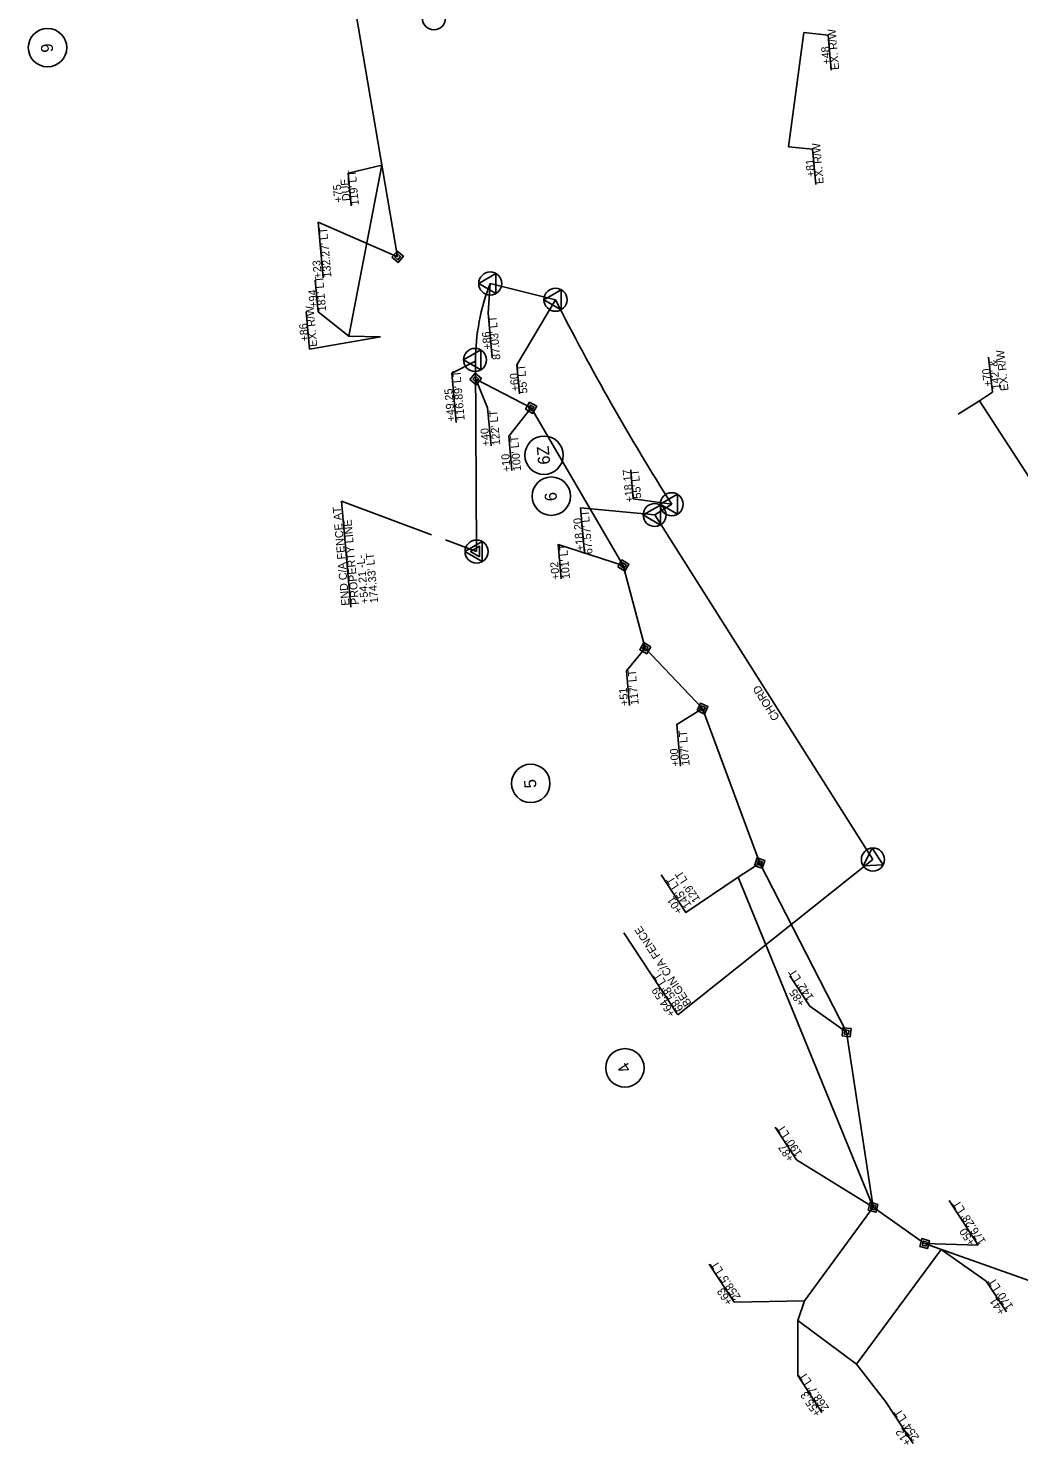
# Model space of a CAD drawing. Extents: x 1555582 to 1558054, y 687961 to 694065.
# Drawn here: x 1555934 to 1556553, y 690007 to 690891 of the extents above; entities that cross this region are included whole.
import ezdxf

# ---------------------------------------------------------------- set-up
doc = ezdxf.new("R2010")
doc.units = 0
for name, color, linetype in [('Exist Horizontal Alignment', 7, 'Continuous'), ('Exist Hydrographic Top of Bank', 7, 'Continuous'), ('Exist Structure Minor Drop Inlet Text', 7, 'Continuous'), ('Prop Approach Slab Hatching', 7, 'Continuous'), ('Prop Drainage Structure Box Reinforced Concrete', 7, 'Continuous'), ('Prop Drainage Structure Catch Basin Grate 840 03F CELL', 7, 'Continuous'), ('Prop Drainage Structure Catch Basin Grate 840 03F Label', 7, 'Continuous'), ('Prop Drainage Structure Catch Basin Grate 840 03G CELL', 7, 'Continuous'), ('Prop Drainage Structure Catch Basin Grate 840 03G Label', 7, 'Continuous'), ('Prop Drainage Structure Plot Symbol 20 Scale', 7, 'Continuous'), ('Prop Drainage Structure Plot Symbol 50 Scale', 7, 'Continuous'), ('Prop Erosion Rip Rap Single Stone CELL', 7, 'Continuous'), ('Prop Plan Preparation Excavation Hatching', 7, 'Continuous'), ('Scratch_Level_1', 7, 'Continuous'), ('Scratch_Level_3', 7, 'Continuous')]:
    doc.layers.add(name, color=color, linetype=linetype)

msp = doc.modelspace()

# ---------------------------------------------------------------- linework, layer by layer
at = {"layer": 'Exist Horizontal Alignment'}
for p, q in [((1556221.68, 690713.43), (1556222.91, 690731.97)), ((1556239.58, 690681.13), (1556263.71, 690721.82)), ((1556221.68, 690713.43), (1556224.19, 690685.55)), ((1556198.93, 690676.02), (1556213.79, 690683.51)), ((1556198.93, 690676.02), (1556201.71, 690645.14)), ((1556239.58, 690681.13), (1556241.21, 690662.97)), ((1556310.69, 690615.55), (1556312.32, 690597.4)), ((1556129.94, 690596.02), (1556135.91, 690529.7)), ((1556129.94, 690596.02), (1556186.21, 690575.01)), ((1556312.32, 690597.4), (1556336.31, 690594.03)), ((1556279.33, 690591.85), (1556281.84, 690563.96)), ((1556279.33, 690591.85), (1556325.67, 690587.34)), ((1556195.01, 690571.73), (1556214.36, 690564.5)), ((1556340.04, 690274.99), (1556462.03, 690372.08)), ((1556306.43, 690326.24), (1556340.04, 690274.99))]:
    msp.add_line(p, q, dxfattribs=at)
at = {"layer": 'Exist Hydrographic Top of Bank'}
for p, q in [((1556377.86, 690361.15), (1556391.27, 690369.87)), ((1556462.08, 690154.86), (1556377.86, 690361.15))]:
    msp.add_line(p, q, dxfattribs=at)
at = {"layer": 'Exist Structure Minor Drop Inlet Text'}
for p, q in [((1556433.97, 690887.19), (1556435.95, 690865.17)), ((1556424.29, 690815.92), (1556426.27, 690793.9)), ((1556134.19, 690800.82), (1556136.02, 690780.45)), ((1556113.63, 690734.06), (1556115.4, 690714.35)), ((1556107.85, 690714.17), (1556109.94, 690690.96)), ((1556400.89, 690204.93), (1556414.3, 690184.48)), ((1556414.3, 690184.48), (1556462.08, 690154.86)), ((1556532.82, 690108.71), (1556504.62, 690128.51)), ((1556359.7, 690119.26), (1556375.29, 690095.5)), ((1556532.82, 690108.71), (1556545.46, 690089.44)), ((1556375.29, 690095.5), (1556419.23, 690096.3)), ((1556415.05, 690049.73), (1556415.18, 690084.1)), ((1556415.05, 690049.73), (1556430.21, 690026.62)), ((1556469.97, 690033.47), (1556487.18, 690007.23))]:
    msp.add_line(p, q, dxfattribs=at)
for points in [[(1556433.97, 690887.19), (1556418.76, 690888.79)], [(1556424.29, 690815.92), (1556409.19, 690817.31)], [(1556134.19, 690800.82), (1556155.29, 690805.82)], [(1556115.4, 690714.35), (1556134.49, 690699)], [(1556109.94, 690690.96), (1556154.35, 690698.68)], [(1556469.97, 690033.47), (1556451.83, 690056.79)]]:
    msp.add_lwpolyline(points, dxfattribs=at)
at = {"layer": 'Prop Approach Slab Hatching'}
for p, q in [((1556165.07, 690748.64), (1556165.07, 690748.64)), ((1556213.85, 690672.28), (1556213.85, 690672.28)), ((1556248.49, 690654.31), (1556248.49, 690654.31)), ((1556306.08, 690555.78), (1556306.08, 690555.78)), ((1556319.82, 690504.12), (1556319.82, 690504.12)), ((1556355.53, 690466.37), (1556355.53, 690466.37)), ((1556462.03, 690372.08), (1556462.03, 690372.08)), ((1556391.27, 690369.87), (1556391.27, 690369.87)), ((1556445.6, 690264.21), (1556445.6, 690264.21)), ((1556462.08, 690154.86), (1556462.08, 690154.86)), ((1556494.35, 690132.14), (1556494.35, 690132.14))]:
    msp.add_line(p, q, dxfattribs=at)
msp.add_lwpolyline([(1556468.47, 690368.83), (1556456.01, 690368.13), (1556461.62, 690379.28)], close=True, dxfattribs=at)
msp.add_circle((1556462.03, 690372.08), 7.2, dxfattribs=at)
at = {"layer": 'Prop Drainage Structure Box Reinforced Concrete'}
for p, q in [((1556409.19, 690817.31), (1556418.76, 690888.79)), ((1556134.49, 690699), (1556155.29, 690805.82)), ((1556154.35, 690698.68), (1556134.49, 690699)), ((1556419.23, 690096.3), (1556462.08, 690154.86)), ((1556451.83, 690056.79), (1556504.62, 690128.51)), ((1556415.18, 690084.1), (1556419.23, 690096.3)), ((1556451.83, 690056.79), (1556415.18, 690084.1))]:
    msp.add_line(p, q, dxfattribs=at)
at = {"layer": 'Prop Drainage Structure Catch Basin Grate 840 03F CELL'}
msp.add_line((1556534.34, 690685.98), (1556536.79, 690664.01), dxfattribs=at)
msp.add_lwpolyline([(1556536.79, 690664.01), (1556528.55, 690658.63)], dxfattribs=at)
at = {"layer": 'Prop Drainage Structure Catch Basin Grate 840 03F Label'}
for p, q in [((1555946.33, 690879.34), (1555946.33, 690879.34)), ((1556256.55, 690624.68), (1556256.55, 690624.68)), ((1556261.09, 690599.11), (1556261.09, 690599.11)), ((1556248.25, 690419.65), (1556248.25, 690419.65)), ((1556307.07, 690241.95), (1556307.07, 690241.95))]:
    msp.add_line(p, q, dxfattribs=at)
for centre in [(1555946.33, 690879.34), (1556256.55, 690624.68), (1556261.09, 690599.11), (1556248.25, 690419.65), (1556307.07, 690241.95)]:
    msp.add_circle(centre, 12, dxfattribs=at)
at = {"layer": 'Prop Drainage Structure Catch Basin Grate 840 03G Label'}
for p, q in [((1556222.91, 690731.97), (1556222.91, 690731.97)), ((1556263.71, 690721.82), (1556263.71, 690721.82)), ((1556213.41, 690684.21), (1556213.41, 690684.21)), ((1556336.31, 690594.03), (1556336.31, 690594.03)), ((1556325.67, 690587.34), (1556325.67, 690587.34))]:
    msp.add_line(p, q, dxfattribs=at)
for points in [[(1556226.5, 690725.72), (1556215.71, 690731.98), (1556226.51, 690738.22)], [(1556267.3, 690715.57), (1556256.51, 690721.83), (1556267.31, 690728.07)], [(1556217, 690677.95), (1556206.21, 690684.22), (1556217.02, 690690.45)], [(1556329.26, 690581.08), (1556318.47, 690587.35), (1556329.28, 690593.58)], [(1556339.9, 690587.78), (1556329.11, 690594.04), (1556339.92, 690600.28)]]:
    msp.add_lwpolyline(points, close=True, dxfattribs=at)
for centre in [(1556222.91, 690731.97), (1556263.71, 690721.82), (1556213.41, 690684.21), (1556325.67, 690587.34), (1556336.31, 690594.03)]:
    msp.add_circle(centre, 7.2, dxfattribs=at)
at = {"layer": 'Prop Drainage Structure Plot Symbol 20 Scale'}
for p, q in [((1556263.71, 690721.82), (1556222.91, 690731.97)), ((1556214.36, 690564.5), (1556213.79, 690683.51)), ((1556325.67, 690587.34), (1556336.31, 690594.03)), ((1556462.03, 690372.08), (1556325.67, 690587.34))]:
    msp.add_line(p, q, dxfattribs=at)
for centre, radius, start, end in [((1556343.87, 690684.13), 130.08, 158.42241, 180.27535), ((1557650.51, 691425.24), 1555, 206.89498, 212.31255)]:
    msp.add_arc(centre, radius, start, end, dxfattribs=at)
at = {"layer": 'Prop Drainage Structure Plot Symbol 50 Scale'}
for p, q in [((1556234.5, 690636.51), (1556248.49, 690654.31)), ((1556236.43, 690615.06), (1556234.5, 690636.51)), ((1556214.36, 690564.5), (1556214.36, 690564.5)), ((1556509.57, 690159.05), (1556527.81, 690131.24))]:
    msp.add_line(p, q, dxfattribs=at)
for points in [[(1556118.56, 690735.41), (1556115.43, 690770.27), (1556165.07, 690748.64)], [(1556223.42, 690630.62), (1556221.3, 690654.21), (1556213.85, 690672.28)], [(1556267.21, 690547.42), (1556265.27, 690568.87), (1556306.08, 690555.78)], [(1556309.99, 690468.42), (1556308.05, 690489.9), (1556319.82, 690504.12)], [(1556341.84, 690430.45), (1556339.5, 690456.47), (1556355.53, 690466.37)], [(1556410.17, 690299.45), (1556422.65, 690280.42), (1556445.6, 690264.21)], [(1556527.81, 690131.24), (1556494.35, 690132.14)]]:
    msp.add_lwpolyline(points, dxfattribs=at)
for points in [[(1556217.96, 690558.25), (1556217.97, 690570.75), (1556207.16, 690564.51)], [(1556216.24, 690561.23), (1556210.6, 690564.51), (1556216.25, 690567.77)]]:
    msp.add_lwpolyline(points, close=True, dxfattribs=at)
for centre in [(1556187.74, 690897.67), (1556214.37, 690564.5)]:
    msp.add_circle(centre, 7.2, dxfattribs=at)
at = {"layer": 'Prop Erosion Rip Rap Single Stone CELL'}
for p, q in [((1556528.55, 690658.63), (1556515.34, 690650.27)), ((1556664.59, 690449.33), (1556528.55, 690658.63))]:
    msp.add_line(p, q, dxfattribs=at)
at = {"layer": 'Prop Plan Preparation Excavation Hatching'}
for p, q in [((1556165.07, 690748.64), (1556132.53, 690938.86)), ((1556248.49, 690654.31), (1556213.85, 690672.28)), ((1556306.08, 690555.78), (1556248.49, 690654.31)), ((1556319.82, 690504.12), (1556306.08, 690555.78)), ((1556355.53, 690466.37), (1556319.82, 690504.12)), ((1556391.27, 690369.87), (1556355.53, 690466.37)), ((1556445.6, 690264.21), (1556391.27, 690369.87)), ((1556462.08, 690154.86), (1556445.6, 690264.21)), ((1556462.08, 690154.86), (1556462.08, 690154.86)), ((1556494.35, 690132.14), (1556462.08, 690154.86)), ((1556616.7, 690088.85), (1556494.35, 690132.14))]:
    msp.add_line(p, q, dxfattribs=at)
at = {"layer": 'Scratch_Level_1'}
msp.add_lwpolyline([(1556329.72, 690362.52), (1556345.09, 690339.09), (1556377.86, 690361.15)], dxfattribs=at)
at = {"layer": 'Scratch_Level_3'}
for points in [[(1556161.49, 690748.32), (1556164.75, 690752.23), (1556168.66, 690748.96), (1556165.39, 690745.05)], [(1556163.28, 690748.48), (1556164.91, 690750.43), (1556166.86, 690748.8), (1556165.23, 690746.85)], [(1556210.26, 690671.96), (1556213.52, 690675.87), (1556217.43, 690672.61), (1556214.17, 690668.7)], [(1556212.05, 690672.12), (1556213.68, 690674.08), (1556215.64, 690672.44), (1556214.01, 690670.49)], [(1556245.01, 690653.39), (1556247.56, 690657.79), (1556251.97, 690655.24), (1556249.41, 690650.83)], [(1556246.75, 690653.85), (1556248.02, 690656.05), (1556250.23, 690654.77), (1556248.95, 690652.57)], [(1556302.6, 690554.85), (1556305.15, 690559.26), (1556309.56, 690556.7), (1556307, 690552.3)], [(1556304.34, 690555.31), (1556305.62, 690557.52), (1556307.82, 690556.24), (1556306.54, 690554.04)], [(1556323.3, 690505.05), (1556320.74, 690500.64), (1556316.34, 690503.2), (1556318.89, 690507.6)], [(1556321.56, 690504.59), (1556320.28, 690502.38), (1556318.08, 690503.66), (1556319.35, 690505.86)], [(1556352.16, 690465.12), (1556354.28, 690469.74), (1556358.91, 690467.62), (1556356.78, 690462.99)], [(1556353.84, 690465.74), (1556354.91, 690468.05), (1556357.22, 690466.99), (1556356.16, 690464.68)], [(1556388.07, 690368.23), (1556389.63, 690373.08), (1556394.48, 690371.52), (1556392.92, 690366.67)], [(1556389.67, 690369.05), (1556390.45, 690371.47), (1556392.87, 690370.7), (1556392.1, 690368.27)], [(1556442.81, 690261.94), (1556443.32, 690267), (1556448.39, 690266.49), (1556447.88, 690261.43)], [(1556444.21, 690263.08), (1556444.46, 690265.61), (1556446.99, 690265.35), (1556446.74, 690262.82)], [(1556458.97, 690153.04), (1556460.26, 690157.96), (1556465.18, 690156.67), (1556463.89, 690151.75)], [(1556460.52, 690153.95), (1556461.17, 690156.41), (1556463.63, 690155.76), (1556462.98, 690153.3)], [(1556491.24, 690130.33), (1556492.53, 690135.25), (1556497.45, 690133.96), (1556496.16, 690129.03)], [(1556492.79, 690131.23), (1556493.44, 690133.7), (1556495.9, 690133.05), (1556495.25, 690130.59)]]:
    msp.add_lwpolyline(points, close=True, dxfattribs=at)

# ---------------------------------------------------------------- texts
at = {"layer": 'Exist Horizontal Alignment'}
for s, rotation, p in [("87.03' LT", 95.14143, (1556229.31, 690684.49)), ('+86', 95.14143, (1556223.67, 690690.88)), ("116.89' LT", 95.14143, (1556206.99, 690646.55)), ('+60', 95.14143, (1556241.02, 690664.85)), ("55' LT", 95.14143, (1556246.22, 690663.4)), ('+49.25', 95.14143, (1556201.01, 690646.01)), ('+18.17', 95.14143, (1556312.48, 690595.43)), ("55' LT", 95.14143, (1556317.33, 690597.83)), ('END C/A FENCE AT ', 95.14143, (1556135.01, 690530.92)), ('PROPERTY LINE', 95.14143, (1556140.99, 690531.46)), ('+18.20', 95.14143, (1556281.63, 690565.1)), ("67.57' LT", 95.14143, (1556286.89, 690563.05)), ('+54.21 -L-', 95.14143, (1556146.96, 690532)), ("174.33' LT", 95.14143, (1556152.94, 690532.54)), ('CHORD', 122.16679, (1556403.9, 690460.79)), ('BEGIN C/A FENCE', 123.26168, (1556348.91, 690282.29)), ("68.58' LT.", 123.26168, (1556343.89, 690279)), ('+64.59', 123.26168, (1556338.87, 690275.71))]:
    msp.add_text(s, height=5, rotation=rotation, dxfattribs=at).set_placement(p)
at = {"layer": 'Exist Structure Minor Drop Inlet Text'}
for s, rotation, p in [('EX. R/W', 95.14143, (1556440.96, 690865.63)), ('+48', 95.14143, (1556435.59, 690868.98)), ('EX. R/W', 95.14143, (1556431.27, 690794.37)), ('+81', 95.14143, (1556425.81, 690798.7)), ('DUE', 95.14143, (1556135.55, 690783.7)), ("119' LT", 95.14143, (1556140.87, 690780.95)), ('+75', 95.14143, (1556130.56, 690782.82)), ("181' LT", 95.14143, (1556120.41, 690714.78)), ('+94', 95.14143, (1556115.13, 690717.14)), ('EX. R/W', 95.14143, (1556114.83, 690692.62)), ('+86', 95.14143, (1556109.46, 690695.98)), ("190' LT", 123.26168, (1556418.03, 690188.55)), ('+87', 123.26168, (1556413.02, 690185.26)), ("258.5' LT", 123.26168, (1556379.63, 690098.8)), ("170' LT", 123.26168, (1556549.94, 690092.89)), ('+63', 123.26168, (1556374.62, 690095.51)), ('+41', 123.26168, (1556544.93, 690089.6)), ("268.7' LT", 123.26168, (1556434.86, 690029.38)), ('+55.3', 123.26168, (1556429.84, 690026.09)), ("254' LT", 123.26168, (1556491.21, 690011.02)), ('+12', 123.26168, (1556486.2, 690007.73))]:
    msp.add_text(s, height=5, rotation=rotation, dxfattribs=at).set_placement(p)
at = {"layer": 'Prop Drainage Structure Catch Basin Grate 840 03F CELL'}
for s, p in [("142' &", (1556541.62, 690666.02)), ('EX. R/W', (1556546.8, 690665.14)), ('+70', (1556536.34, 690667.81))]:
    msp.add_text(s, height=5, rotation=96.3743, dxfattribs=at).set_placement(p)
at = {"layer": 'Prop Drainage Structure Catch Basin Grate 840 03G CELL'}
for s, rotation, p in [('9', 95.14143, (1555949.98, 690876.62)), ('6Z', 95.14143, (1556260.44, 690619.14)), ('6', 95.14143, (1556264.73, 690596.35)), ('5', 95.14143, (1556251.88, 690417.02)), ('4', 123.26168, (1556311.31, 690241.51))]:
    msp.add_text(s, height=7.5, rotation=rotation, dxfattribs=at).set_placement(p)
at = {"layer": 'Prop Drainage Structure Plot Symbol 50 Scale'}
for s, rotation, p in [("132.27' LT", 95.14143, (1556123.74, 690735.95)), ('+23', 95.14143, (1556117.76, 690735.42)), ("122' LT", 95.14143, (1556229.23, 690631.12)), ('+40', 95.14143, (1556222.75, 690630.53)), ("100' LT", 95.14143, (1556242.24, 690615.05)), ('+10', 95.14143, (1556235.77, 690614.46)), ("101' LT", 95.14143, (1556272.79, 690547.56)), ('+02', 95.14143, (1556266.31, 690546.98)), ("117' LT", 95.14143, (1556315.71, 690468.94)), ('+51', 95.14143, (1556309.24, 690468.36)), ("107' LT", 95.14143, (1556347.57, 690430.96)), ('+00', 95.14143, (1556341.09, 690430.38)), ("142' LT", 123.26168, (1556425.27, 690285.91)), ('+85', 123.26168, (1556419.83, 690282.34)), (" 176.28' LT  ", 123.26168, (1556533.85, 690132)), ('+50', 123.26168, (1556526.07, 690132.91))]:
    msp.add_text(s, height=5, rotation=rotation, dxfattribs=at).set_placement(p)
at = {"layer": 'Scratch_Level_1'}
for s, p in [("129' LT", (1556354.3, 690347.21)), ("145' LT", (1556348.87, 690343.65)), ('+01', (1556343.43, 690340.08))]:
    msp.add_text(s, height=5, rotation=123.26168, dxfattribs=at).set_placement(p)

doc.saveas('drawing.dxf')
